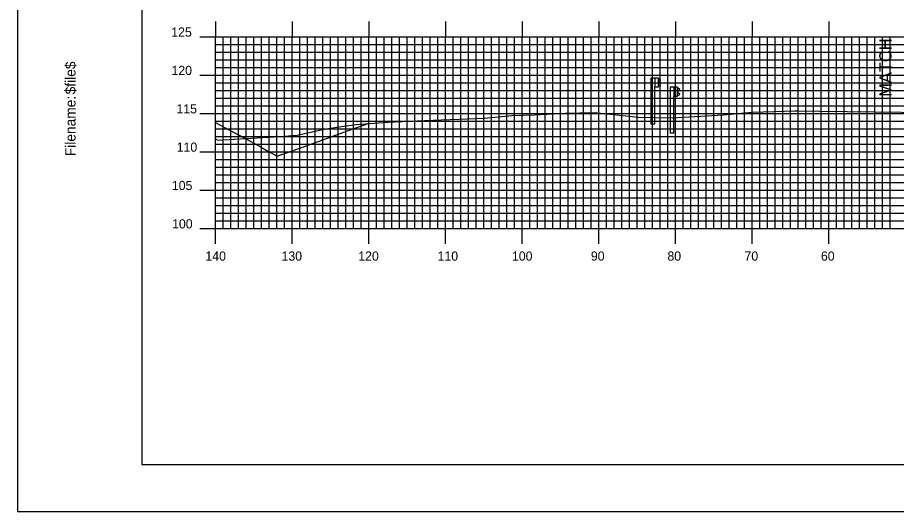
# Model space of a CAD drawing. Extents: x 1754708 to 1755051, y 442591 to 442811.
# Drawn here: x 1754707.7 to 1754822.3, y 442590.5 to 442654.9 of the extents above; entities that cross this region are included whole.
import ezdxf

# ---------------------------------------------------------------- set-up
doc = ezdxf.new("R2010")
doc.units = 0
for name, color, linetype in [('ANNOTATION', 7, 'Continuous'), ('BORDER', 7, 'Continuous'), ('H_V ANNOTATION', 7, 'Continuous'), ('M_Guardrail', 7, 'Continuous'), ('M_Roadway_Centerline', 7, 'Continuous'), ('MAJOR', 7, 'Continuous'), ('MINOR', 7, 'Continuous'), ('PLOT BOUNDARY', 7, 'Continuous'), ('S_Roadway_Centerline', 7, 'Continuous')]:
    doc.layers.add(name, color=color, linetype=linetype)

msp = doc.modelspace()

# ---------------------------------------------------------------- linework, layer by layer
at = {"layer": 'BORDER'}
msp.add_lwpolyline([(1754723.92, 442596.67), (1755043.92, 442596.67), (1755043.92, 442806.67), (1754723.92, 442806.67)], close=True, dxfattribs=at)
at = {"layer": 'M_Guardrail'}
for p, q in [((1754790.32, 442647.05), (1754790.32, 442641.05)), ((1754790.81, 442647.05), (1754790.32, 442647.05)), ((1754791.3, 442647.05), (1754790.81, 442647.05)), ((1754790.81, 442647.05), (1754790.81, 442645.88)), ((1754791.3, 442645.88), (1754791.3, 442647.05)), ((1754791.3, 442646.98), (1754791.38, 442646.96)), ((1754791.31, 442646.51), (1754791.31, 442646.42)), ((1754791.54, 442646.71), (1754791.35, 442646.58)), ((1754791.35, 442646.36), (1754791.54, 442646.22)), ((1754791.4, 442646.96), (1754791.54, 442646.86)), ((1754790.81, 442641.05), (1754790.81, 442645.88)), ((1754790.81, 442645.88), (1754791.3, 442645.88)), ((1754791.38, 442645.97), (1754791.3, 442645.96)), ((1754791.54, 442646.08), (1754791.4, 442645.98)), ((1754792.81, 442645.84), (1754792.81, 442639.84)), ((1754793.3, 442645.84), (1754792.81, 442645.84)), ((1754793.79, 442645.84), (1754793.3, 442645.84)), ((1754793.3, 442645.84), (1754793.3, 442644.68)), ((1754793.79, 442644.68), (1754793.79, 442645.84)), ((1754793.79, 442645.77), (1754793.88, 442645.76)), ((1754793.81, 442645.31), (1754793.81, 442645.21)), ((1754794.04, 442645.51), (1754793.84, 442645.37)), ((1754793.84, 442645.15), (1754794.04, 442645.01)), ((1754793.89, 442645.75), (1754794.04, 442645.65)), ((1754793.3, 442639.84), (1754793.3, 442644.68)), ((1754793.3, 442644.68), (1754793.79, 442644.68)), ((1754793.88, 442644.76), (1754793.79, 442644.75)), ((1754794.04, 442644.87), (1754793.89, 442644.77)), ((1754790.81, 442641.05), (1754790.32, 442641.05)), ((1754793.3, 442639.84), (1754792.81, 442639.84))]:
    msp.add_line(p, q, dxfattribs=at)
for centre, major_axis, start_param, end_param in [((1754791.39, 442646.51), (-0.0789, 0), 5.323254, 6.283185), ((1754791.39, 442646.42), (-0.0789, 0), 6.283185, 7.243116), ((1754791.38, 442646.92), (0.0417, 0), 0.959931, 1.396263), ((1754791.49, 442646.78), (0.0877, 0), 5.323254, 7.243116), ((1754791.49, 442646.15), (0.0877, 0), 5.323254, 7.243116), ((1754791.38, 442646.01), (0.0417, 0), 4.886922, 5.323254), ((1754793.89, 442645.31), (-0.0789, 0), 5.323254, 6.283185), ((1754793.89, 442645.21), (-0.0789, 0), 6.283185, 7.243116), ((1754793.87, 442645.71), (0.0417, 0), 0.959931, 1.396263), ((1754793.99, 442645.58), (0.0877, 0), 5.323254, 7.243116), ((1754793.87, 442644.8), (0.0417, 0), 4.886922, 5.323254), ((1754793.99, 442644.94), (0.0877, 0), 5.323254, 7.243116)]:
    msp.add_ellipse(centre, major_axis=major_axis, ratio=0.995501, start_param=start_param, end_param=end_param, dxfattribs=at)
at = {"layer": 'MAJOR'}
for p, q in [((1754733.52, 442654.44), (1754733.52, 442652.44)), ((1754743.52, 442654.44), (1754743.52, 442652.44)), ((1754753.52, 442654.44), (1754753.52, 442652.44)), ((1754763.52, 442654.44), (1754763.52, 442652.44)), ((1754773.52, 442654.44), (1754773.52, 442652.44)), ((1754783.52, 442654.44), (1754783.52, 442652.44)), ((1754793.52, 442654.44), (1754793.52, 442652.44)), ((1754803.52, 442654.44), (1754803.52, 442652.44)), ((1754813.52, 442654.44), (1754813.52, 442652.44)), ((1754731.51, 442652.44), (1754733.52, 442652.44)), ((1754733.52, 442652.44), (1755013.52, 442652.44)), ((1754733.52, 442627.44), (1754733.52, 442652.44)), ((1754733.52, 442627.44), (1754733.52, 442652.44)), ((1754733.52, 442652.44), (1755013.52, 442652.44)), ((1754743.52, 442627.44), (1754743.52, 442652.44)), ((1754753.52, 442627.44), (1754753.52, 442652.44)), ((1754763.52, 442627.44), (1754763.52, 442652.44)), ((1754773.52, 442627.44), (1754773.52, 442652.44)), ((1754783.52, 442627.44), (1754783.52, 442652.44)), ((1754793.52, 442627.44), (1754793.52, 442652.44)), ((1754803.52, 442627.44), (1754803.52, 442652.44)), ((1754813.52, 442627.44), (1754813.52, 442652.44)), ((1754731.51, 442647.44), (1754733.52, 442647.44)), ((1754733.52, 442647.44), (1755013.52, 442647.44)), ((1754731.51, 442642.44), (1754733.52, 442642.44)), ((1754733.52, 442642.44), (1755013.52, 442642.44)), ((1754731.51, 442637.44), (1754733.52, 442637.44)), ((1754733.52, 442637.44), (1755013.52, 442637.44)), ((1754731.51, 442632.44), (1754733.52, 442632.44)), ((1754733.52, 442632.44), (1755013.52, 442632.44)), ((1754731.51, 442627.44), (1754733.52, 442627.44)), ((1754733.52, 442627.44), (1755013.52, 442627.44)), ((1754733.52, 442627.44), (1755013.52, 442627.44)), ((1754733.52, 442625.43), (1754733.52, 442627.44)), ((1754743.52, 442625.43), (1754743.52, 442627.44)), ((1754753.52, 442625.43), (1754753.52, 442627.44)), ((1754763.52, 442625.43), (1754763.52, 442627.44)), ((1754773.52, 442625.43), (1754773.52, 442627.44)), ((1754783.52, 442625.43), (1754783.52, 442627.44)), ((1754793.52, 442625.43), (1754793.52, 442627.44)), ((1754803.52, 442625.43), (1754803.52, 442627.44)), ((1754813.52, 442625.43), (1754813.52, 442627.44))]:
    msp.add_line(p, q, dxfattribs=at)
at = {"layer": 'MINOR'}
for p, q in [((1754734.52, 442627.44), (1754734.52, 442652.44)), ((1754735.52, 442627.44), (1754735.52, 442652.44)), ((1754736.52, 442627.44), (1754736.52, 442652.44)), ((1754737.52, 442627.44), (1754737.52, 442652.44)), ((1754738.52, 442627.44), (1754738.52, 442652.44)), ((1754739.52, 442627.44), (1754739.52, 442652.44)), ((1754740.52, 442627.44), (1754740.52, 442652.44)), ((1754741.52, 442627.44), (1754741.52, 442652.44)), ((1754742.52, 442627.44), (1754742.52, 442652.44)), ((1754744.52, 442627.44), (1754744.52, 442652.44)), ((1754745.52, 442627.44), (1754745.52, 442652.44)), ((1754746.52, 442627.44), (1754746.52, 442652.44)), ((1754747.52, 442627.44), (1754747.52, 442652.44)), ((1754748.52, 442627.44), (1754748.52, 442652.44)), ((1754749.52, 442627.44), (1754749.52, 442652.44)), ((1754750.52, 442627.44), (1754750.52, 442652.44)), ((1754751.52, 442627.44), (1754751.52, 442652.44)), ((1754752.52, 442627.44), (1754752.52, 442652.44)), ((1754754.52, 442627.44), (1754754.52, 442652.44)), ((1754755.52, 442627.44), (1754755.52, 442652.44)), ((1754756.52, 442627.44), (1754756.52, 442652.44)), ((1754757.52, 442627.44), (1754757.52, 442652.44)), ((1754758.52, 442627.44), (1754758.52, 442652.44)), ((1754759.52, 442627.44), (1754759.52, 442652.44)), ((1754760.52, 442627.44), (1754760.52, 442652.44)), ((1754761.52, 442627.44), (1754761.52, 442652.44)), ((1754762.52, 442627.44), (1754762.52, 442652.44)), ((1754764.52, 442627.44), (1754764.52, 442652.44)), ((1754765.52, 442627.44), (1754765.52, 442652.44)), ((1754766.52, 442627.44), (1754766.52, 442652.44)), ((1754767.52, 442627.44), (1754767.52, 442652.44)), ((1754768.52, 442627.44), (1754768.52, 442652.44)), ((1754769.52, 442627.44), (1754769.52, 442652.44)), ((1754770.52, 442627.44), (1754770.52, 442652.44)), ((1754771.52, 442627.44), (1754771.52, 442652.44)), ((1754772.52, 442627.44), (1754772.52, 442652.44)), ((1754774.52, 442627.44), (1754774.52, 442652.44)), ((1754775.52, 442627.44), (1754775.52, 442652.44)), ((1754776.52, 442627.44), (1754776.52, 442652.44)), ((1754777.52, 442627.44), (1754777.52, 442652.44)), ((1754778.52, 442627.44), (1754778.52, 442652.44)), ((1754779.52, 442627.44), (1754779.52, 442652.44)), ((1754780.52, 442627.44), (1754780.52, 442652.44)), ((1754781.52, 442627.44), (1754781.52, 442652.44)), ((1754782.52, 442627.44), (1754782.52, 442652.44)), ((1754784.52, 442627.44), (1754784.52, 442652.44)), ((1754785.52, 442627.44), (1754785.52, 442652.44)), ((1754786.52, 442627.44), (1754786.52, 442652.44)), ((1754787.52, 442627.44), (1754787.52, 442652.44)), ((1754788.52, 442627.44), (1754788.52, 442652.44)), ((1754789.52, 442627.44), (1754789.52, 442652.44)), ((1754790.52, 442627.44), (1754790.52, 442652.44)), ((1754791.52, 442627.44), (1754791.52, 442652.44)), ((1754792.52, 442627.44), (1754792.52, 442652.44)), ((1754794.52, 442627.44), (1754794.52, 442652.44)), ((1754795.52, 442627.44), (1754795.52, 442652.44)), ((1754796.52, 442627.44), (1754796.52, 442652.44)), ((1754797.52, 442627.44), (1754797.52, 442652.44)), ((1754798.52, 442627.44), (1754798.52, 442652.44)), ((1754799.52, 442627.44), (1754799.52, 442652.44)), ((1754800.52, 442627.44), (1754800.52, 442652.44)), ((1754801.52, 442627.44), (1754801.52, 442652.44)), ((1754802.52, 442627.44), (1754802.52, 442652.44)), ((1754804.52, 442627.44), (1754804.52, 442652.44)), ((1754805.52, 442627.44), (1754805.52, 442652.44)), ((1754806.52, 442627.44), (1754806.52, 442652.44)), ((1754807.52, 442627.44), (1754807.52, 442652.44)), ((1754808.52, 442627.44), (1754808.52, 442652.44)), ((1754809.52, 442627.44), (1754809.52, 442652.44)), ((1754810.52, 442627.44), (1754810.52, 442652.44)), ((1754811.52, 442627.44), (1754811.52, 442652.44)), ((1754812.52, 442627.44), (1754812.52, 442652.44)), ((1754814.52, 442627.44), (1754814.52, 442652.44)), ((1754815.52, 442627.44), (1754815.52, 442652.44)), ((1754816.52, 442627.44), (1754816.52, 442652.44)), ((1754817.52, 442627.44), (1754817.52, 442652.44)), ((1754818.52, 442627.44), (1754818.52, 442652.44)), ((1754819.52, 442627.44), (1754819.52, 442652.44)), ((1754820.52, 442627.44), (1754820.52, 442652.44)), ((1754821.52, 442627.44), (1754821.52, 442652.44)), ((1754733.52, 442651.44), (1755013.52, 442651.44)), ((1754733.52, 442651.44), (1754735.52, 442651.44)), ((1754733.52, 442650.44), (1755013.52, 442650.44)), ((1754733.52, 442650.44), (1754735.52, 442650.44)), ((1754733.52, 442649.44), (1755013.52, 442649.44)), ((1754733.52, 442649.44), (1754735.52, 442649.44)), ((1754733.52, 442648.44), (1755013.52, 442648.44)), ((1754733.52, 442648.44), (1754735.52, 442648.44)), ((1754733.52, 442646.44), (1755013.52, 442646.44)), ((1754733.52, 442646.44), (1754735.52, 442646.44)), ((1754733.52, 442645.44), (1755013.52, 442645.44)), ((1754733.52, 442645.44), (1754735.52, 442645.44)), ((1754733.52, 442644.44), (1755013.52, 442644.44)), ((1754733.52, 442644.44), (1754735.52, 442644.44)), ((1754733.52, 442643.44), (1755013.52, 442643.44)), ((1754733.52, 442643.44), (1754735.52, 442643.44)), ((1754733.52, 442641.44), (1755013.52, 442641.44)), ((1754733.52, 442641.44), (1754735.52, 442641.44)), ((1754733.52, 442640.44), (1755013.52, 442640.44)), ((1754733.52, 442640.44), (1754735.52, 442640.44)), ((1754733.52, 442639.44), (1755013.52, 442639.44)), ((1754733.52, 442639.44), (1754735.52, 442639.44)), ((1754733.52, 442638.44), (1755013.52, 442638.44)), ((1754733.52, 442638.44), (1754735.52, 442638.44)), ((1754733.52, 442636.44), (1755013.52, 442636.44)), ((1754733.52, 442636.44), (1754735.52, 442636.44)), ((1754733.52, 442635.44), (1755013.52, 442635.44)), ((1754733.52, 442635.44), (1754735.52, 442635.44)), ((1754733.52, 442634.44), (1755013.52, 442634.44)), ((1754733.52, 442634.44), (1754735.52, 442634.44)), ((1754733.52, 442633.44), (1755013.52, 442633.44)), ((1754733.52, 442633.44), (1754735.52, 442633.44)), ((1754733.52, 442631.44), (1755013.52, 442631.44)), ((1754733.52, 442631.44), (1754735.52, 442631.44)), ((1754733.52, 442630.44), (1755013.52, 442630.44)), ((1754733.52, 442630.44), (1754735.52, 442630.44)), ((1754733.52, 442629.44), (1755013.52, 442629.44)), ((1754733.52, 442629.44), (1754735.52, 442629.44)), ((1754733.52, 442628.44), (1755013.52, 442628.44)), ((1754733.52, 442628.44), (1754735.52, 442628.44))]:
    msp.add_line(p, q, dxfattribs=at)
at = {"layer": 'PLOT BOUNDARY'}
msp.add_lwpolyline([(1754707.73, 442590.55), (1755047.73, 442590.55), (1755047.73, 442810.55), (1754707.73, 442810.55)], close=True, dxfattribs=at)
at = {"layer": 'S_Roadway_Centerline'}
for points in [[(1754733.52, 442639.12), (1754733.84, 442638.96), (1754741.89, 442639.41), (1754744.19, 442639.58), (1754747.48, 442640.33), (1754749.35, 442640.64), (1754751.87, 442640.98), (1754756.03, 442641.29), (1754760.78, 442641.51), (1754767.5, 442641.78), (1754768.55, 442641.82), (1754768.64, 442641.82), (1754772.17, 442642.16), (1754775.13, 442642.26), (1754779.13, 442642.46), (1754782.94, 442642.57), (1754788.68, 442641.96), (1754793.09, 442641.84), (1754799.73, 442642.24), (1754803.56, 442642.6), (1754809.1, 442642.77), (1754809.36, 442642.78), (1754809.57, 442642.78), (1754812.36, 442642.73), (1754826.57, 442642.54)], [(1754733.52, 442641.26), (1754734.39, 442640.79), (1754735.37, 442640.26), (1754736.79, 442639.5), (1754739.42, 442638.06), (1754740.46, 442637.49), (1754740.8, 442637.3), (1754741.57, 442636.88), (1754742.93, 442637.35), (1754745.02, 442638.1), (1754747.52, 442639), (1754750.16, 442639.94), (1754753.46, 442641.1)]]:
    msp.add_lwpolyline(points, dxfattribs=at)

# ---------------------------------------------------------------- texts
at = {"layer": 'ANNOTATION'}
msp.add_text('MATCH', height=1.6, rotation=90, dxfattribs=at).set_placement((1754821.7, 442644.6))
at = {"layer": 'BORDER'}
for s, p in [('$file$', (1754715.29, 442644.92)), ('$file$', (1754715.29, 442644.92)), ('Filename:', (1754715.29, 442636.86)), ('Filename:', (1754715.29, 442636.86))]:
    msp.add_text(s, height=1.339, rotation=90, dxfattribs=at).set_placement(p)
at = {"layer": 'H_V ANNOTATION'}
for s, p in [('125', (1754727.77, 442652.44)), ('120', (1754727.8, 442647.44)), ('115', (1754728.45, 442642.44)), ('110', (1754728.48, 442637.44)), ('105', (1754727.85, 442632.44)), ('100', (1754727.88, 442627.44)), ('140', (1754732.22, 442623.24)), ('130', (1754742.15, 442623.24)), ('120', (1754752.16, 442623.24)), ('110', (1754762.5, 442623.24)), ('100', (1754772.2, 442623.24)), ('90', (1754782.49, 442623.24)), ('80', (1754792.47, 442623.24)), ('70', (1754802.52, 442623.24)), ('60', (1754812.49, 442623.24))]:
    msp.add_text(s, height=1.2, dxfattribs=at).set_placement(p)
at = {"layer": 'M_Roadway_Centerline'}
for s, p in [('L', (1754809.35, 442642.77)), ('C', (1754809.36, 442642.78)), ('C', (1754772.16, 442642.16)), ('L', (1754772.16, 442642.15))]:
    msp.add_text(s, height=0.0146, dxfattribs=at).set_placement(p)
at = {"layer": 'MAJOR'}
msp.add_text('-', height=0.012, dxfattribs=at).set_placement((1754733.51, 442627.44))

doc.saveas('drawing.dxf')
